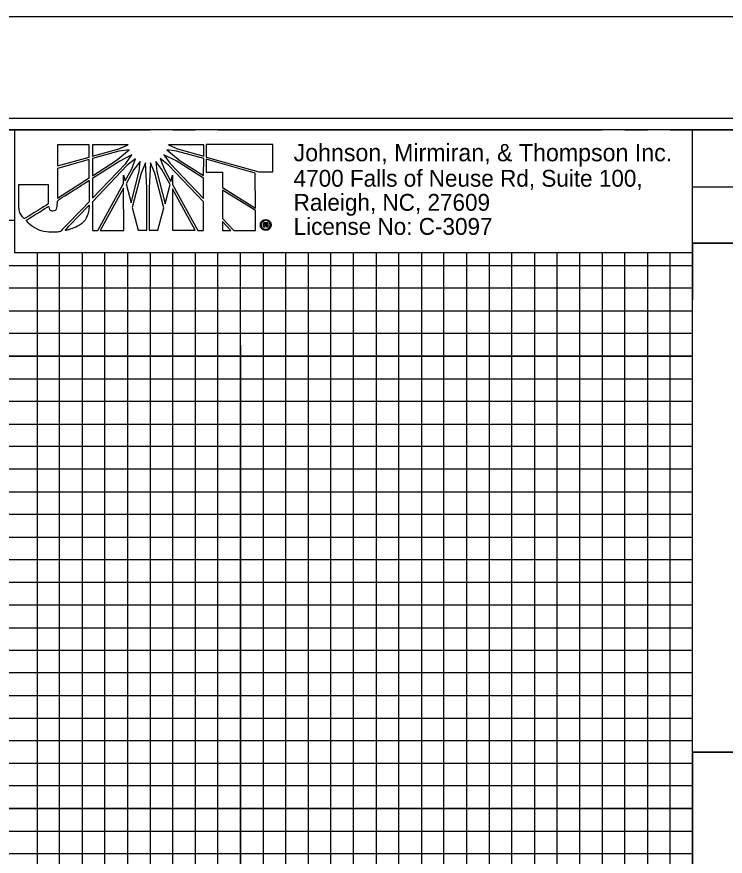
# Model space of a CAD drawing. Extents: x 1648157 to 1650776, y 832691 to 834781.
# Drawn here: x 1650179.7 to 1650336.4, y 833605.5 to 833791 of the extents above; entities that cross this region are included whole.
import ezdxf

# ---------------------------------------------------------------- set-up
doc = ezdxf.new("R2010")
doc.units = 0
for name, color, linetype in [('Prop Dimension Text', 7, 'Continuous'), ('Sheet Cutting Line CELL', 7, 'Continuous'), ('Sheet DOT Grid CELL', 7, 'Continuous'), ('Sheet Plan CELL', 7, 'Continuous'), ('Sheet Plot Border Inside CELL', 7, 'Continuous'), ('Sheet Plot Border Outside CELL', 7, 'Continuous'), ('Sheet Profile CELL', 7, 'Continuous'), ('Sheet Profile Grid Major CELL', 7, 'Continuous'), ('Sheet Profile Grid Middle CELL', 7, 'Continuous'), ('Sheet Profile Grid Minor CELL', 7, 'Continuous'), ('Sheet Sticker Exception Certification CELL', 7, 'Continuous')]:
    doc.layers.add(name, color=color, linetype=linetype)

msp = doc.modelspace()

# ---------------------------------------------------------------- linework, layer by layer
at = {"layer": 'Prop Dimension Text'}
for p, q in [((1650195.74, 833762.71), (1650188.72, 833762.7)), ((1650188.72, 833762.7), (1650188.72, 833758.05)), ((1650195.74, 833760), (1650195.74, 833762.71)), ((1650204.36, 833762.75), (1650196.47, 833762.75)), ((1650196.47, 833762.75), (1650196.47, 833760.23)), ((1650202.35, 833761.86), (1650204.36, 833762.75)), ((1650221.09, 833762.73), (1650213.3, 833762.76)), ((1650213.3, 833762.76), (1650215.27, 833761.84)), ((1650221.09, 833760.21), (1650221.09, 833762.73)), ((1650236.38, 833762.78), (1650221.63, 833762.77)), ((1650221.63, 833762.77), (1650221.63, 833760.06)), ((1650236.39, 833756.74), (1650236.38, 833762.78)), ((1650196.47, 833760.23), (1650202.35, 833761.86)), ((1650202.35, 833761.31), (1650196.47, 833759.69)), ((1650201.74, 833759.23), (1650204.64, 833761.59)), ((1650204.64, 833761.59), (1650202.35, 833761.31)), ((1650205.22, 833760.51), (1650202.55, 833759.15)), ((1650203.87, 833758.61), (1650205.22, 833760.51)), ((1650212.3, 833760.51), (1650213.66, 833758.58)), ((1650215.01, 833759.16), (1650212.3, 833760.51)), ((1650212.91, 833761.6), (1650215.85, 833759.2)), ((1650215.08, 833761.33), (1650212.91, 833761.6)), ((1650221.09, 833759.68), (1650215.08, 833761.33)), ((1650215.27, 833761.84), (1650221.09, 833760.21)), ((1650188.72, 833758.05), (1650195.74, 833760)), ((1650195.74, 833759.49), (1650188.72, 833757.52)), ((1650195.74, 833755.43), (1650195.74, 833759.49)), ((1650196.47, 833759.69), (1650196.47, 833755.89)), ((1650196.47, 833755.89), (1650201.74, 833759.23)), ((1650202.55, 833759.15), (1650196.47, 833755.28)), ((1650206.03, 833759.66), (1650204.17, 833758.22)), ((1650205.18, 833757.42), (1650206.03, 833759.66)), ((1650207.04, 833759.04), (1650205.65, 833757.25)), ((1650206.85, 833756.87), (1650207.04, 833759.04)), ((1650208.2, 833758.73), (1650207.24, 833756.48)), ((1650208.51, 833753.19), (1650208.2, 833758.73)), ((1650209.36, 833758.73), (1650209, 833753.19)), ((1650210.29, 833756.48), (1650209.36, 833758.73)), ((1650210.48, 833759.04), (1650210.72, 833756.8)), ((1650211.84, 833757.26), (1650210.48, 833759.04)), ((1650211.48, 833759.67), (1650212.34, 833757.42)), ((1650213.34, 833758.23), (1650211.48, 833759.67)), ((1650221.05, 833755.33), (1650215.01, 833759.16)), ((1650215.85, 833759.2), (1650221.05, 833755.96)), ((1650221.05, 833755.96), (1650221.09, 833759.68)), ((1650221.63, 833760.06), (1650221.63, 833759.98)), ((1650221.63, 833759.98), (1650233.25, 833756.74)), ((1650221.63, 833759.56), (1650221.63, 833759.52)), ((1650232.51, 833756.47), (1650221.63, 833759.56)), ((1650221.63, 833759.52), (1650221.64, 833756.69)), ((1650188.72, 833757.52), (1650188.73, 833750.97)), ((1650196.48, 833750.9), (1650203.87, 833758.61)), ((1650204.17, 833758.22), (1650196.48, 833750.16)), ((1650203.71, 833754.74), (1650205.18, 833757.42)), ((1650205.65, 833757.25), (1650203.91, 833754.08)), ((1650205.04, 833749.87), (1650206.85, 833756.87)), ((1650210.72, 833756.8), (1650212.54, 833749.71)), ((1650213.66, 833753.97), (1650211.84, 833757.26)), ((1650212.34, 833757.42), (1650213.84, 833754.63)), ((1650221.05, 833750.11), (1650213.34, 833758.23)), ((1650213.66, 833758.58), (1650221.05, 833750.84)), ((1650188.73, 833750.97), (1650195.74, 833755.43)), ((1650196.47, 833755.28), (1650196.48, 833750.9)), ((1650203.36, 833754.16), (1650203.36, 833756.01)), ((1650203.36, 833756.01), (1650203.71, 833754.74)), ((1650207.24, 833756.48), (1650205.27, 833748.89)), ((1650212.31, 833748.78), (1650210.29, 833756.48)), ((1650213.84, 833754.63), (1650214.2, 833756.02)), ((1650214.2, 833756.02), (1650214.2, 833753.97)), ((1650221.05, 833750.84), (1650221.05, 833755.33)), ((1650221.64, 833756.69), (1650225.24, 833756.69)), ((1650225.24, 833756.69), (1650225.24, 833753.32)), ((1650232.52, 833748.72), (1650232.51, 833756.47)), ((1650233.25, 833756.74), (1650236.39, 833756.74)), ((1650197.64, 833743.79), (1650203.36, 833754.16)), ((1650203.37, 833753.15), (1650198.19, 833743.79)), ((1650203.42, 833743.8), (1650203.37, 833753.15)), ((1650203.91, 833754.08), (1650205.04, 833749.87)), ((1650208.52, 833743.84), (1650208.51, 833753.19)), ((1650209, 833753.19), (1650209.01, 833743.84)), ((1650212.54, 833749.71), (1650213.66, 833753.97)), ((1650214.2, 833753.97), (1650219.82, 833743.81)), ((1650225.24, 833753.32), (1650232.52, 833748.72)), ((1650219.24, 833743.85), (1650214.2, 833752.97)), ((1650214.2, 833752.97), (1650214.21, 833743.84)), ((1650225.24, 833752.74), (1650225.25, 833746.47)), ((1650232.52, 833748.18), (1650225.24, 833752.74)), ((1650196.48, 833750.16), (1650196.48, 833743.79)), ((1650221.06, 833743.81), (1650221.05, 833750.11)), ((1650205.27, 833748.89), (1650206.59, 833743.83)), ((1650210.96, 833743.84), (1650212.31, 833748.78)), ((1650232.52, 833743.82), (1650232.52, 833748.18)), ((1650225.25, 833746.47), (1650227.76, 833743.82)), ((1650227.07, 833743.82), (1650225.25, 833745.78)), ((1650225.25, 833745.78), (1650225.25, 833743.82)), ((1650234.81, 833746.19), (1650234.81, 833745.97)), ((1650234.81, 833745.97), (1650234.81, 833746.19)), ((1650196.48, 833743.79), (1650197.64, 833743.79)), ((1650198.19, 833743.79), (1650203.42, 833743.8)), ((1650206.59, 833743.83), (1650208.52, 833743.84)), ((1650209.01, 833743.84), (1650210.96, 833743.84)), ((1650214.21, 833743.84), (1650219.24, 833743.85)), ((1650219.82, 833743.81), (1650221.06, 833743.81)), ((1650225.25, 833743.82), (1650227.07, 833743.82)), ((1650227.76, 833743.82), (1650232.52, 833743.82)), ((1650234.37, 833744.49), (1650234.37, 833745.56)), ((1650234.37, 833745.56), (1650234.81, 833745.56)), ((1650234.61, 833744.49), (1650234.37, 833744.49)), ((1650234.81, 833745.36), (1650234.61, 833745.36)), ((1650234.61, 833745.36), (1650234.61, 833745.1)), ((1650234.61, 833745.1), (1650234.81, 833745.1)), ((1650234.81, 833744.91), (1650234.61, 833744.91)), ((1650234.61, 833744.91), (1650234.61, 833744.49)), ((1650234.81, 833745.56), (1650234.81, 833745.36)), ((1650234.81, 833745.36), (1650234.81, 833745.56)), ((1650234.81, 833745.56), (1650234.87, 833745.56)), ((1650234.84, 833745.36), (1650234.81, 833745.36)), ((1650234.81, 833745.1), (1650234.81, 833744.91)), ((1650234.81, 833744.91), (1650234.81, 833745.1)), ((1650234.81, 833745.1), (1650234.82, 833745.1)), ((1650234.82, 833744.91), (1650234.81, 833744.91)), ((1650234.81, 833744.07), (1650234.81, 833743.83)), ((1650234.81, 833743.83), (1650234.81, 833744.07)), ((1650234.81, 833744.07), (1650234.82, 833744.07)), ((1650234.82, 833743.83), (1650234.81, 833743.83))]:
    msp.add_line(p, q, dxfattribs=at)
msp.add_lwpolyline([(1650179.23, 833738.96), (1650329.18, 833738.96), (1650329.18, 833766.02), (1650179.23, 833766.02)], close=True, dxfattribs=at)
for points in [[(1650188.72, 833758.05), (1650195.74, 833760), (1650195.74, 833762.71), (1650188.72, 833762.7), (1650188.72, 833758.05)], [(1650202.35, 833761.86), (1650204.36, 833762.75), (1650196.47, 833762.75), (1650196.47, 833760.23), (1650202.35, 833761.86)], [(1650215.27, 833761.84), (1650221.09, 833760.21), (1650221.09, 833762.73), (1650213.3, 833762.76), (1650215.27, 833761.84)], [(1650236.38, 833762.78), (1650221.63, 833762.77), (1650221.63, 833760.06), (1650221.63, 833759.98), (1650233.25, 833756.74), (1650236.39, 833756.74), (1650236.38, 833762.78)], [(1650196.47, 833759.69), (1650196.47, 833755.89), (1650201.74, 833759.23), (1650204.64, 833761.59), (1650202.35, 833761.31), (1650196.47, 833759.69)], [(1650196.47, 833755.28), (1650196.48, 833750.9), (1650203.87, 833758.61), (1650205.22, 833760.51), (1650202.55, 833759.15), (1650196.47, 833755.28)], [(1650212.3, 833760.51), (1650213.66, 833758.58), (1650221.05, 833750.84), (1650221.05, 833755.33), (1650215.01, 833759.16), (1650212.3, 833760.51)], [(1650212.91, 833761.6), (1650215.85, 833759.2), (1650221.05, 833755.96), (1650221.09, 833759.68), (1650215.08, 833761.33), (1650212.91, 833761.6)], [(1650188.73, 833750.97), (1650195.74, 833755.43), (1650195.74, 833759.49), (1650188.72, 833757.52), (1650188.73, 833750.97)], [(1650206.03, 833759.66), (1650204.17, 833758.22), (1650196.48, 833750.16), (1650196.48, 833743.79), (1650197.64, 833743.79), (1650203.36, 833754.16), (1650203.36, 833756.01), (1650203.71, 833754.74), (1650205.18, 833757.42), (1650206.03, 833759.66)], [(1650207.04, 833759.04), (1650205.65, 833757.25), (1650203.91, 833754.08), (1650205.04, 833749.87), (1650206.85, 833756.87), (1650207.04, 833759.04)], [(1650207.24, 833756.48), (1650205.27, 833748.89), (1650206.59, 833743.83), (1650208.52, 833743.84), (1650208.51, 833753.19), (1650208.2, 833758.73), (1650207.24, 833756.48)], [(1650209.36, 833758.73), (1650209, 833753.19), (1650209.01, 833743.84), (1650210.96, 833743.84), (1650212.31, 833748.78), (1650210.29, 833756.48), (1650209.36, 833758.73)], [(1650210.48, 833759.04), (1650210.72, 833756.8), (1650212.54, 833749.71), (1650213.66, 833753.97), (1650211.84, 833757.26), (1650210.48, 833759.04)], [(1650211.48, 833759.67), (1650212.34, 833757.42), (1650213.84, 833754.63), (1650214.2, 833756.02), (1650214.2, 833753.97), (1650219.82, 833743.81), (1650221.06, 833743.81), (1650221.05, 833750.11), (1650213.34, 833758.23), (1650211.48, 833759.67)], [(1650221.63, 833759.56), (1650221.63, 833759.52), (1650221.64, 833756.69), (1650225.24, 833756.69), (1650225.24, 833753.32), (1650232.52, 833748.72), (1650232.51, 833756.47), (1650221.63, 833759.56)], [(1650198.19, 833743.79), (1650203.42, 833743.8), (1650203.37, 833753.15), (1650198.19, 833743.79)], [(1650214.21, 833743.84), (1650219.24, 833743.85), (1650214.2, 833752.97), (1650214.21, 833743.84)], [(1650225.24, 833752.74), (1650225.25, 833746.47), (1650227.76, 833743.82), (1650232.52, 833743.82), (1650232.52, 833748.18), (1650225.24, 833752.74), (1650225.24, 833752.74)], [(1650225.25, 833743.82), (1650225.25, 833743.82), (1650227.07, 833743.82), (1650225.25, 833745.78), (1650225.25, 833743.82)], [(1650235.28, 833744.74), (1650235.28, 833744.68), (1650235.28, 833744.64), (1650235.28, 833744.61), (1650235.31, 833744.49), (1650235.09, 833744.49)]]:
    msp.add_lwpolyline(points, dxfattribs=at)
for points, degree in [([(1650186.71, 833753.98), (1650186.71, 833753.98), (1650180.22, 833753.98), (1650180.22, 833753.98), (1650180.22, 833753.98), (1650180.22, 833749.91), (1650180.22, 833749.91), (1650180.22, 833749.91), (1650180.22, 833749.48), (1650180.22, 833749.48), (1650180.22, 833748.21), (1650180.64, 833747.2), (1650181.38, 833746.36), (1650181.38, 833746.36), (1650186.72, 833749.6), (1650186.72, 833749.69), (1650186.72, 833749.69), (1650186.71, 833753.98), (1650186.71, 833753.98)], 3), ([(1650187.73, 833748.13), (1650187.31, 833748.13), (1650186.95, 833748.37), (1650186.8, 833749.14), (1650186.8, 833749.14), (1650181.76, 833746.02), (1650181.76, 833746.02), (1650183.32, 833744.39), (1650185.8, 833743.42), (1650187.89, 833743.42), (1650188.44, 833743.42), (1650188.85, 833743.47), (1650189.43, 833743.59), (1650189.43, 833743.59), (1650195.75, 833750.12), (1650195.75, 833750.12), (1650195.75, 833750.12), (1650195.74, 833754.85), (1650195.74, 833754.85), (1650195.74, 833754.85), (1650188.73, 833750.38), (1650188.73, 833750.38), (1650188.73, 833748.61), (1650188.3, 833748.14), (1650187.73, 833748.13)], 3), ([(1650187.73, 833748.13), (1650187.31, 833748.13), (1650186.95, 833748.37), (1650186.8, 833749.14), (1650186.8, 833749.14), (1650181.76, 833746.02), (1650181.76, 833746.02), (1650183.32, 833744.39), (1650185.8, 833743.42), (1650187.89, 833743.42), (1650188.44, 833743.42), (1650188.85, 833743.47), (1650189.43, 833743.59), (1650189.43, 833743.59), (1650195.75, 833750.12), (1650195.75, 833750.12), (1650195.75, 833750.12), (1650195.74, 833754.85), (1650195.74, 833754.85), (1650195.74, 833754.85), (1650188.73, 833750.38), (1650188.73, 833750.38), (1650188.73, 833748.61), (1650188.3, 833748.14), (1650187.73, 833748.13)], 3), ([(1650195.75, 833749.38), (1650195.75, 833749.38), (1650190.29, 833743.74), (1650190.29, 833743.74), (1650192.96, 833744.4), (1650195.63, 833746.17), (1650195.75, 833749.38)], 3), ([(1650234.81, 833743.83), (1650234.49, 833743.83), (1650234.2, 833743.95), (1650233.97, 833744.18), (1650233.73, 833744.41), (1650233.62, 833744.69), (1650233.62, 833745.02), (1650233.62, 833745.35), (1650233.73, 833745.64), (1650233.97, 833745.85), (1650234.2, 833746.08), (1650234.47, 833746.19), (1650234.81, 833746.19)], 3), ([(1650234.81, 833745.97), (1650234.54, 833745.97), (1650234.32, 833745.88), (1650234.13, 833745.71), (1650233.95, 833745.52), (1650233.85, 833745.29), (1650233.85, 833745.02), (1650233.85, 833744.76), (1650233.95, 833744.53), (1650234.13, 833744.34), (1650234.32, 833744.16), (1650234.54, 833744.07), (1650234.81, 833744.07)], 3), ([(1650234.81, 833746.19), (1650235.14, 833746.19), (1650235.42, 833746.08), (1650235.65, 833745.85), (1650235.89, 833745.64), (1650236.01, 833745.36), (1650236.01, 833745.03)], 3), ([(1650234.82, 833744.07), (1650235.08, 833744.07), (1650235.3, 833744.16), (1650235.49, 833744.34), (1650235.67, 833744.53), (1650235.77, 833744.76), (1650235.77, 833745.03), (1650235.77, 833745.29), (1650235.67, 833745.52), (1650235.49, 833745.71), (1650235.3, 833745.88), (1650235.08, 833745.97), (1650234.81, 833745.97)], 3), ([(1650234.82, 833745.1), (1650234.97, 833745.1), (1650235.05, 833745.15), (1650235.05, 833745.24), (1650235.05, 833745.32), (1650234.98, 833745.36), (1650234.84, 833745.36)], 3), ([(1650236.01, 833745.03), (1650236.01, 833744.69), (1650235.89, 833744.41), (1650235.67, 833744.18), (1650235.43, 833743.95), (1650235.15, 833743.83), (1650234.82, 833743.83)], 3), ([(1650235, 833744.87), (1650234.97, 833744.89), (1650234.91, 833744.91), (1650234.82, 833744.91)], 2), ([(1650234.87, 833745.56), (1650235.15, 833745.56), (1650235.28, 833745.45), (1650235.28, 833745.24), (1650235.28, 833745.14), (1650235.25, 833745.06), (1650235.16, 833745)], 3), ([(1650235.09, 833744.49), (1650235.06, 833744.55), (1650235.04, 833744.61), (1650235.04, 833744.68), (1650235.04, 833744.78), (1650235.03, 833744.84), (1650235, 833744.87)], 3), ([(1650235.16, 833745), (1650235.23, 833744.97), (1650235.27, 833744.88), (1650235.28, 833744.74)], 2)]:
    msp.add_open_spline(points, degree=degree, dxfattribs=at)
at = {"layer": 'Sheet Cutting Line CELL'}
msp.add_line((1650546.28, 833791.02), (1648862.28, 833791.02), dxfattribs=at)
at = {"layer": 'Sheet DOT Grid CELL'}
for p, q in [((1650229.28, 833266.02), (1650229.28, 833718.48)), ((1650279.28, 833266.02), (1650279.28, 833718.48)), ((1650329.23, 833716.02), (1649029.28, 833716.02)), ((1650329.23, 833666.02), (1649029.28, 833666.02)), ((1650329.28, 833266.02), (1650329.28, 833628.47)), ((1650329.28, 833616.02), (1649029.28, 833616.02))]:
    msp.add_line(p, q, dxfattribs=at)
at = {"layer": 'Sheet Plan CELL'}
for p, q in [((1650329.18, 833740.94), (1650329.18, 833728.45)), ((1650329.18, 833740.94), (1650329.18, 833728.45)), ((1650329.23, 833740.94), (1650329.23, 833728.45))]:
    msp.add_line(p, q, dxfattribs=at)
at = {"layer": 'Sheet Plot Border Inside CELL'}
msp.add_lwpolyline([(1648875.28, 832713.47), (1650541.78, 832713.47), (1650541.78, 833768.57), (1648875.28, 833768.57)], close=True, dxfattribs=at)
at = {"layer": 'Sheet Plot Border Outside CELL'}
msp.add_lwpolyline([(1648862.28, 832691.02), (1650546.28, 832691.02), (1650546.28, 833791.02), (1648862.28, 833791.02)], close=True, dxfattribs=at)
at = {"layer": 'Sheet Profile CELL'}
msp.add_line((1650329.23, 833753.47), (1650529.28, 833753.47), dxfattribs=at)
for points in [[(1650529.28, 833766.02), (1649029.28, 833766.02), (1649029.28, 832716.02), (1650529.28, 832716.02)], [(1650329.23, 833766.02), (1650529.28, 833766.02), (1650529.28, 833740.97), (1650329.23, 833740.97)], [(1650329.23, 833740.97), (1650429.28, 833740.97), (1650429.28, 833628.47), (1650329.23, 833628.47)]]:
    msp.add_lwpolyline(points, close=True, dxfattribs=at)
at = {"layer": 'Sheet Profile Grid Major CELL'}
for points in [[(1650229.23, 833766.02), (1650279.23, 833766.02)], [(1650279.23, 833738.96), (1650279.23, 833266.02), (1650329.23, 833266.02), (1650329.23, 833766.02), (1650355.53, 833766.02)], [(1650179.23, 833266.02), (1650229.23, 833266.02), (1650229.23, 833738.96)], [(1649029.23, 833716.02), (1650329.23, 833716.02)], [(1650329.23, 833666.02), (1649029.23, 833666.02), (1649029.23, 833616.02), (1650329.23, 833616.02)]]:
    msp.add_lwpolyline(points, dxfattribs=at)
at = {"layer": 'Sheet Profile Grid Middle CELL'}
for points in [[(1650154.23, 833766.02), (1650204.23, 833766.02)], [(1650254.23, 833766.02), (1650304.23, 833766.02)], [(1650204.23, 833738.96), (1650204.23, 833266.02), (1650254.23, 833266.02), (1650254.23, 833738.96)], [(1650304.23, 833738.96), (1650304.23, 833266.02), (1650354.23, 833266.02), (1650354.23, 833604.97)], [(1650329.23, 833691.02), (1649029.23, 833691.02), (1649029.23, 833641.02), (1650329.23, 833641.02)]]:
    msp.add_lwpolyline(points, dxfattribs=at)
at = {"layer": 'Sheet Profile Grid Minor CELL'}
for p, q in [((1650329.18, 833761.02), (1650329.23, 833761.02)), ((1650329.23, 833756.02), (1650329.18, 833756.02)), ((1650329.18, 833751.02), (1650329.23, 833751.02)), ((1650329.18, 833631.02), (1649079.23, 833631.02)), ((1650329.23, 833626.02), (1649079.23, 833626.02)), ((1650329.23, 833621.02), (1649079.23, 833621.02)), ((1649079.23, 833611.02), (1650329.23, 833611.02)), ((1650329.23, 833606.02), (1649079.23, 833606.02))]:
    msp.add_line(p, q, dxfattribs=at)
for points in [[(1650174.23, 833766.02), (1650184.23, 833766.02)], [(1650189.23, 833766.02), (1650194.23, 833766.02)], [(1650199.23, 833766.02), (1650209.23, 833766.02)], [(1650214.23, 833766.02), (1650219.23, 833766.02)], [(1650224.23, 833766.02), (1650234.23, 833766.02)], [(1650239.23, 833766.02), (1650244.23, 833766.02)], [(1650249.23, 833766.02), (1650259.23, 833766.02)], [(1650264.23, 833766.02), (1650269.23, 833766.02)], [(1650274.23, 833766.02), (1650284.23, 833766.02)], [(1650289.23, 833766.02), (1650294.23, 833766.02)], [(1650299.23, 833766.02), (1650309.23, 833766.02)], [(1650314.23, 833766.02), (1650319.23, 833766.02)], [(1650324.23, 833766.02), (1650334.23, 833766.02)], [(1650179.23, 833746.02), (1649079.23, 833746.02), (1649079.23, 833736.02), (1650329.23, 833736.02)], [(1650329.23, 833746.02), (1650329.18, 833746.02)], [(1650184.23, 833738.96), (1650184.23, 833266.02), (1650189.23, 833266.02), (1650189.23, 833738.96)], [(1650194.23, 833738.96), (1650194.23, 833266.02), (1650199.23, 833266.02), (1650199.23, 833738.96)], [(1650209.23, 833738.96), (1650209.23, 833266.02), (1650214.23, 833266.02), (1650214.23, 833738.96)], [(1650219.23, 833266.02), (1650224.23, 833266.02), (1650224.23, 833738.96)], [(1650219.23, 833738.96), (1650219.23, 833266.02)], [(1650234.23, 833738.96), (1650234.23, 833266.02), (1650239.23, 833266.02), (1650239.23, 833738.96)], [(1650244.23, 833738.96), (1650244.23, 833266.02), (1650249.23, 833266.02), (1650249.23, 833738.96)], [(1650259.23, 833738.96), (1650259.23, 833266.02), (1650264.23, 833266.02), (1650264.23, 833738.96)], [(1650269.23, 833738.96), (1650269.23, 833266.02), (1650274.23, 833266.02), (1650274.23, 833738.96)], [(1650284.23, 833738.96), (1650284.23, 833266.02), (1650289.23, 833266.02), (1650289.23, 833738.96)], [(1650294.23, 833738.96), (1650294.23, 833266.02), (1650299.23, 833266.02), (1650299.23, 833738.96)], [(1650309.23, 833738.96), (1650309.23, 833266.02), (1650314.23, 833266.02), (1650314.23, 833738.96)], [(1650319.23, 833738.96), (1650319.23, 833266.02), (1650324.23, 833266.02), (1650324.23, 833738.96)], [(1650329.18, 833731.02), (1649079.23, 833731.02), (1649079.23, 833726.02), (1650329.23, 833726.02)], [(1650329.23, 833721.02), (1649079.23, 833721.02), (1649079.23, 833711.02), (1650329.23, 833711.02)], [(1650329.23, 833706.02), (1649079.23, 833706.02), (1649079.23, 833701.02), (1650329.23, 833701.02)], [(1650329.23, 833696.02), (1649079.23, 833696.02), (1649079.23, 833686.02), (1650329.23, 833686.02)], [(1650329.23, 833681.02), (1649079.23, 833681.02), (1649079.23, 833676.02), (1650329.23, 833676.02)], [(1650329.23, 833671.02), (1649079.23, 833671.02), (1649079.23, 833661.02), (1650329.23, 833661.02)], [(1650329.23, 833655.92), (1649079.33, 833655.92), (1649079.33, 833651.02), (1650329.23, 833651.02)], [(1650329.23, 833646.02), (1649079.23, 833646.02), (1649079.23, 833636.02), (1650329.23, 833636.02)]]:
    msp.add_lwpolyline(points, dxfattribs=at)
at = {"layer": 'Sheet Sticker Exception Certification CELL'}
for p, q in [((1650329.23, 833604.97), (1650329.23, 833628.47)), ((1650329.23, 833628.47), (1650529.27, 833628.47)), ((1650329.23, 833604.97), (1650329.23, 833628.47)), ((1650329.23, 833628.47), (1650529.27, 833628.47))]:
    msp.add_line(p, q, dxfattribs=at)

# ---------------------------------------------------------------- texts
at = {"layer": 'Prop Dimension Text'}
for s, height, p in [('Johnson, Mirmiran, & Thompson Inc.', 3.8315, (1650240.98, 833759.09)), ('4700 Falls of Neuse Rd, Suite 100, ', 3.722, (1650240.98, 833753.47)), ('Raleigh, NC, 27609', 3.722, (1650240.98, 833748.15)), ('License No: C-3097', 3.722, (1650240.98, 833742.83))]:
    msp.add_text(s, height=height, rotation=360, dxfattribs=at).set_placement(p)

doc.saveas('drawing.dxf')
